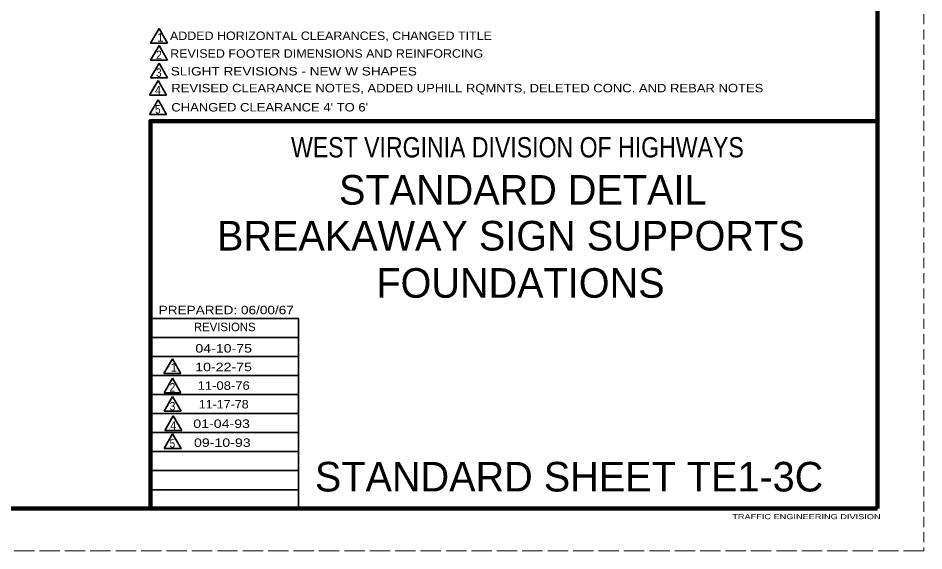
# Model space of a CAD drawing. Extents: x -2 to 678, y -1 to 439.
# Drawn here: x 464.2 to 678.1, y -0.7 to 125.2 of the extents above; entities that cross this region are included whole.
import ezdxf
from ezdxf.enums import TextEntityAlignment as Align

# ---------------------------------------------------------------- set-up
doc = ezdxf.new("R2010")
doc.units = 0
doc.header["$LTSCALE"] = 0.8
doc.linetypes.add('LONG_DASHED', pattern=[7.5, 6, -1.5])
doc.linetypes.add('MEDIUM_DASHED', pattern=[4.5, 3, -1.5])
doc.layers.add('1', color=7, linetype='Continuous', lineweight=35)
doc.layers.add('61', color=7, linetype='Continuous', lineweight=35)

msp = doc.modelspace()

# ---------------------------------------------------------------- linework, layer by layer
at = {"layer": '1', "linetype": 'MEDIUM_DASHED', "lineweight": 13}
msp.add_line((678.0955, 439.3337), (678.0755, -0.6863), dxfattribs=at)
at = {"layer": '1'}
for p, q in [((497.5052, 122.7109), (495.5052, 119.2468)), ((497.5052, 122.7109), (499.5052, 119.2468)), ((499.5052, 119.2468), (495.5052, 119.2468)), ((497.5052, 118.7126), (495.5052, 115.2485)), ((497.5052, 118.7126), (499.5052, 115.2485)), ((497.5042, 114.552), (495.5042, 111.0879)), ((499.5052, 115.2485), (495.5052, 115.2485)), ((497.5042, 114.552), (499.5042, 111.0879)), ((497.2742, 110.4112), (495.2742, 106.9471)), ((499.5042, 111.0879), (495.5042, 111.0879)), ((497.2742, 110.4112), (499.2742, 106.9471)), ((499.2742, 106.9471), (495.2742, 106.9471)), ((497.2742, 105.8858), (495.2742, 102.4217)), ((497.2742, 105.8858), (499.2742, 102.4217)), ((499.2742, 102.4217), (495.2742, 102.4217)), ((530.4755, 49.7337), (495.4955, 49.7337)), ((530.4755, 45.2337), (495.4955, 45.2337)), ((500.6815, 44.6507), (498.6815, 41.1866)), ((500.6815, 44.6507), (502.6815, 41.1866)), ((530.4755, 40.7337), (495.4955, 40.7337)), ((502.6815, 41.1866), (498.6815, 41.1866)), ((500.6887, 40.1217), (498.6887, 36.6577)), ((500.6887, 40.1217), (502.6887, 36.6577)), ((502.6887, 36.6577), (498.6887, 36.6577)), ((530.4755, 36.2137), (495.4955, 36.2137)), ((500.7269, 35.7643), (498.7269, 32.3002)), ((500.7269, 35.7643), (502.7269, 32.3002)), ((502.7269, 32.3002), (498.7269, 32.3002)), ((530.4755, 31.7337), (495.4955, 31.7337)), ((500.885, 31.2185), (498.885, 27.7544)), ((500.885, 31.2185), (502.885, 27.7544)), ((530.4755, 27.2537), (495.4955, 27.2537)), ((500.7035, 26.9522), (498.7035, 23.4882)), ((502.885, 27.7544), (498.885, 27.7544)), ((530.4755, 22.7537), (495.4955, 22.7537)), ((530.4755, 18.2537), (495.4955, 18.2537)), ((530.4755, 13.7337), (495.4955, 13.7337))]:
    msp.add_line(p, q, dxfattribs=at)
at = {"layer": '1', "lineweight": 158}
msp.add_lwpolyline([(495.4755, 9.2937), (495.4755, 100.8737), (667.1355, 100.8737)], dxfattribs=at)
at = {"layer": '1'}
for points in [[(530.4755, 9.2537), (530.4755, 54.2137), (495.4955, 54.2137)], [(500.7035, 26.9522), (502.7035, 23.4882), (498.7035, 23.4882)]]:
    msp.add_lwpolyline(points, dxfattribs=at)
at = {"layer": '61', "lineweight": 158}
for p, q in [((667.1155, 429.3337), (667.1355, 9.2937)), ((667.1355, 9.2937), (28.0755, 9.3137))]:
    msp.add_line(p, q, dxfattribs=at)
at = {"layer": '61', "linetype": 'LONG_DASHED', "lineweight": 13}
msp.add_line((678.0755, -0.6863), (-1.9845, -0.7063), dxfattribs=at)

# ---------------------------------------------------------------- texts
at = {"layer": '1'}
for s, height, width, p in [('ADDED HORIZONTAL CLEARANCES, CHANGED TITLE', 2, 1.1, (500.0913, 120.0156)), ('REVISED FOOTER DIMENSIONS AND REINFORCING', 2, 1.1, (500.1456, 115.8263)), ('2', 2, 0.9, (496.8278, 115.4998)), ('SLIGHT REVISIONS - NEW W SHAPES', 2, 1.2, (500.2544, 111.6369)), ('3', 2, 0.9, (496.7735, 111.3105)), ('4', 2, 0.95, (496.5435, 107.1697)), ('REVISED CLEARANCE NOTES, ADDED UPHILL RQMNTS, DELETED CONC. AND REBAR NOTES', 2, 1.15, (500.4077, 107.6494)), ("CHANGED CLEARANCE 4' TO 6'", 2, 1.15, (500.4077, 103.124)), ('5', 2, 0.9, (496.5435, 102.6442)), ('PREPARED: 06/00/67', 1.998, 1.2, (497.4355, 55.2137)), ('2', 2, 0.9, (500.0017, 36.9331)), ('3', 2, 0.9, (500.0207, 32.4925)), ('4', 2, 0.95, (500.1787, 27.9467)), ('5', 2, 0.9, (499.9973, 23.6804)), ('TRAFFIC ENGINEERING DIVISION', 1.2, 1.35, (632.8555, 6.7937))]:
    msp.add_text(s, height=height, dxfattribs=dict(at, width=width)).set_placement(p)
for s, height, p in [('1', 2, (497.0998, 119.6347)), ('REVISIONS', 1.998, (505.7555, 51.2137)), ('1', 2, (500.2684, 41.6596)), ('STANDARD SHEET TE1-3C', 6.993, (534.3155, 13.3337))]:
    msp.add_text(s, height=height, dxfattribs=at).set_placement(p)
for s, height, width, p in [('WEST VIRGINIA DIVISION OF HIGHWAYS', 4.795, 0.85, (582.1238, 92.2737)), ('04-10-75', 2, 1.25, (512.7755, 46.1537)), ('10-22-75', 2, 1.25, (512.7555, 41.7537)), ('11-08-76', 2, 1.15, (512.7755, 37.3537)), ('11-17-78', 2, 1.1, (512.7755, 32.9537)), ('01-04-93', 2, 1.25, (512.2848, 28.3537)), ('09-10-93', 2, 1.25, (512.4448, 23.8737))]:
    msp.add_text(s, height=height, dxfattribs=dict(at, width=width)).set_placement(p, align=Align.CENTER)
for s, p in [('STANDARD DETAIL', (583.3925, 81.1137)), ('BREAKAWAY SIGN SUPPORTS', (580.5553, 70.2759)), ('FOUNDATIONS', (582.8533, 59.1099))]:
    msp.add_text(s, height=6.993, dxfattribs=at).set_placement(p, align=Align.CENTER)

doc.saveas('drawing.dxf')
